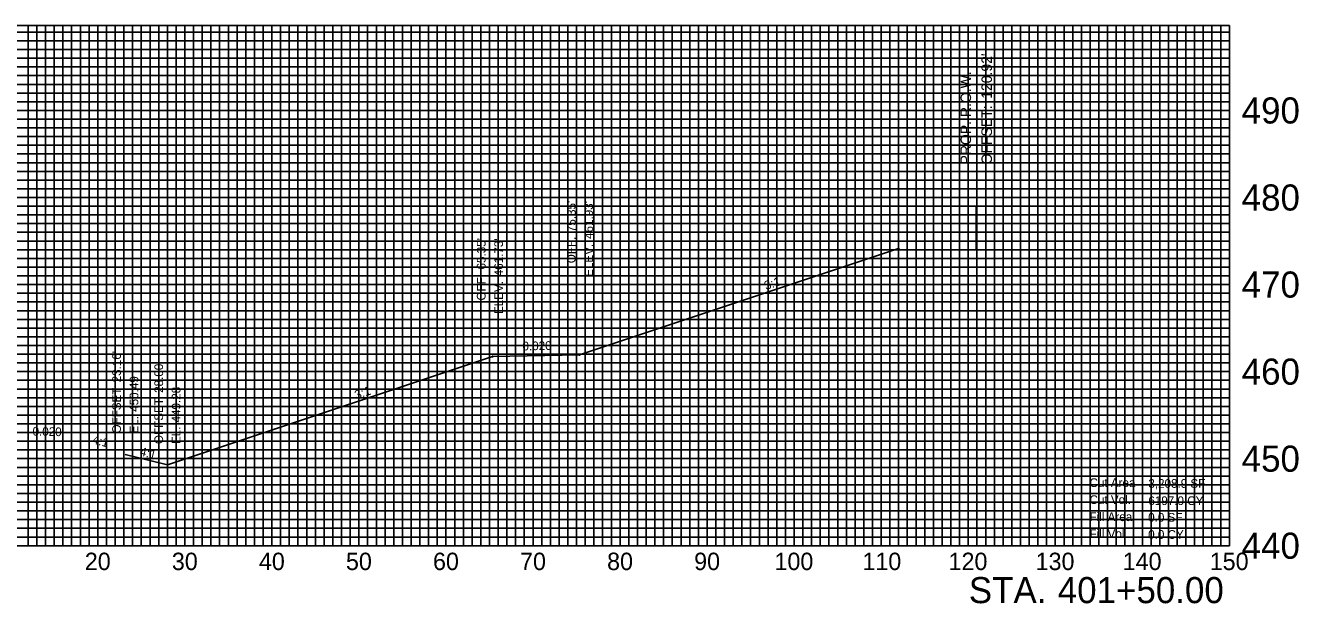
# Model space of a CAD drawing. Extents: x -158 to 158, y 433 to 504.
# Drawn here: x 11.7 to 157.9, y 433.4 to 499.8 of the extents above; entities that cross this region are included whole.
import ezdxf

# ---------------------------------------------------------------- set-up
doc = ezdxf.new("R2010")
doc.units = 0
for name, color, linetype in [('_CIVIL_CONSTRUCTION', 7, 'Continuous'), ('DES - MODEL - CPNT - Grass', 7, 'Continuous'), ('DES - ROW - Linework', 7, 'Continuous'), ('DES - SHEET - Light Grid', 7, 'Continuous'), ('DES - SHEET - Linework', 7, 'Continuous'), ('DES - XS - Earthwork - Cut Text', 7, 'Continuous'), ('DES - XS - Earthwork - Fill Text', 7, 'Continuous'), ('DES - XS - Proposed - Finished Grade Slopes Text', 7, 'Continuous'), ('DES - XS - Proposed - Text', 7, 'Continuous')]:
    doc.layers.add(name, color=color, linetype=linetype)

msp = doc.modelspace()

# ---------------------------------------------------------------- linework, layer by layer
at = {"layer": '_CIVIL_CONSTRUCTION'}
for centre in [(65.35, 461.73), (75.35, 461.93)]:
    msp.add_circle(centre, 0.05, dxfattribs=at)
at = {"layer": 'DES - MODEL - CPNT - Grass'}
for p, q in [((75.35, 461.93), (112.12, 474.18)), ((28, 449.28), (65.35, 461.73)), ((65.35, 461.73), (75.35, 461.93)), ((23.16, 450.49), (28, 449.28))]:
    msp.add_line(p, q, dxfattribs=at)
at = {"layer": 'DES - ROW - Linework'}
msp.add_line((120.92, 473.96), (120.92, 478.88), dxfattribs=at)
at = {"layer": 'DES - SHEET - Light Grid'}
for p, q in [((-150, 499), (150, 499)), ((12, 440), (12, 499.76)), ((13, 440), (13, 499.76)), ((14, 440), (14, 499.76)), ((15, 440), (15, 499.76)), ((16, 440), (16, 499.76)), ((17, 440), (17, 499.76)), ((18, 440), (18, 499.76)), ((19, 440), (19, 499.76)), ((21, 440), (21, 499.76)), ((22, 440), (22, 499.76)), ((23, 440), (23, 499.76)), ((24, 440), (24, 499.76)), ((25, 440), (25, 499.76)), ((26, 440), (26, 499.76)), ((27, 440), (27, 499.76)), ((28, 440), (28, 499.76)), ((29, 440), (29, 499.76)), ((31, 440), (31, 499.76)), ((32, 440), (32, 499.76)), ((33, 440), (33, 499.76)), ((34, 440), (34, 499.76)), ((35, 440), (35, 499.76)), ((36, 440), (36, 499.76)), ((37, 440), (37, 499.76)), ((38, 440), (38, 499.76)), ((39, 440), (39, 499.76)), ((41, 440), (41, 499.76)), ((42, 440), (42, 499.76)), ((43, 440), (43, 499.76)), ((44, 440), (44, 499.76)), ((45, 440), (45, 499.76)), ((46, 440), (46, 499.76)), ((47, 440), (47, 499.76)), ((48, 440), (48, 499.76)), ((49, 440), (49, 499.76)), ((51, 440), (51, 499.76)), ((52, 440), (52, 499.76)), ((53, 440), (53, 499.76)), ((54, 440), (54, 499.76)), ((55, 440), (55, 499.76)), ((56, 440), (56, 499.76)), ((57, 440), (57, 499.76)), ((58, 440), (58, 499.76)), ((59, 440), (59, 499.76)), ((61, 440), (61, 499.76)), ((62, 440), (62, 499.76)), ((63, 440), (63, 499.76)), ((64, 440), (64, 499.76)), ((65, 440), (65, 499.76)), ((66, 440), (66, 499.76)), ((67, 440), (67, 499.76)), ((68, 440), (68, 499.76)), ((69, 440), (69, 499.76)), ((71, 440), (71, 499.76)), ((72, 440), (72, 499.76)), ((73, 440), (73, 499.76)), ((74, 440), (74, 499.76)), ((75, 440), (75, 499.76)), ((76, 440), (76, 499.76)), ((77, 440), (77, 499.76)), ((78, 440), (78, 499.76)), ((79, 440), (79, 499.76)), ((81, 440), (81, 499.76)), ((82, 440), (82, 499.76)), ((83, 440), (83, 499.76)), ((84, 440), (84, 499.76)), ((85, 440), (85, 499.76)), ((86, 440), (86, 499.76)), ((87, 440), (87, 499.76)), ((88, 440), (88, 499.76)), ((89, 440), (89, 499.76)), ((91, 440), (91, 499.76)), ((92, 440), (92, 499.76)), ((93, 440), (93, 499.76)), ((94, 440), (94, 499.76)), ((95, 440), (95, 499.76)), ((96, 440), (96, 499.76)), ((97, 440), (97, 499.76)), ((98, 440), (98, 499.76)), ((99, 440), (99, 499.76)), ((101, 440), (101, 499.76)), ((102, 440), (102, 499.76)), ((103, 440), (103, 499.76)), ((104, 440), (104, 499.76)), ((105, 440), (105, 499.76)), ((106, 440), (106, 499.76)), ((107, 440), (107, 499.76)), ((108, 440), (108, 499.76)), ((109, 440), (109, 499.76)), ((111, 440), (111, 499.76)), ((112, 440), (112, 499.76)), ((113, 440), (113, 499.76)), ((114, 440), (114, 499.76)), ((115, 440), (115, 499.76)), ((116, 440), (116, 499.76)), ((117, 440), (117, 499.76)), ((118, 440), (118, 499.76)), ((119, 440), (119, 499.76)), ((121, 440), (121, 499.76)), ((122, 440), (122, 499.76)), ((123, 440), (123, 499.76)), ((124, 440), (124, 499.76)), ((125, 440), (125, 499.76)), ((126, 440), (126, 499.76)), ((127, 440), (127, 499.76)), ((128, 440), (128, 499.76)), ((129, 440), (129, 499.76)), ((131, 440), (131, 499.76)), ((132, 440), (132, 499.76)), ((133, 440), (133, 499.76)), ((134, 440), (134, 499.76)), ((135, 440), (135, 499.76)), ((136, 440), (136, 499.76)), ((137, 440), (137, 499.76)), ((138, 440), (138, 499.76)), ((139, 440), (139, 499.76)), ((141, 440), (141, 499.76)), ((142, 440), (142, 499.76)), ((143, 440), (143, 499.76)), ((144, 440), (144, 499.76)), ((145, 440), (145, 499.76)), ((146, 440), (146, 499.76)), ((147, 440), (147, 499.76)), ((148, 440), (148, 499.76)), ((149, 440), (149, 499.76)), ((-150, 498), (150, 498)), ((-150, 497), (150, 497)), ((-150, 496), (150, 496)), ((-150, 495), (150, 495)), ((-150, 494), (150, 494)), ((-150, 493), (150, 493)), ((-150, 492), (150, 492)), ((-150, 491), (150, 491)), ((-150, 489), (150, 489)), ((-150, 488), (150, 488)), ((-150, 487), (150, 487)), ((-150, 486), (150, 486)), ((-150, 485), (150, 485)), ((-150, 484), (150, 484)), ((-150, 483), (150, 483)), ((-150, 482), (150, 482)), ((-150, 481), (150, 481)), ((-150, 479), (150, 479)), ((-150, 478), (150, 478)), ((-150, 477), (150, 477)), ((-150, 476), (150, 476)), ((-150, 475), (150, 475)), ((-150, 474), (150, 474)), ((-150, 473), (150, 473)), ((-150, 472), (150, 472)), ((-150, 471), (150, 471)), ((-150, 469), (150, 469)), ((-150, 468), (150, 468)), ((-150, 467), (150, 467)), ((-150, 466), (150, 466)), ((-150, 465), (150, 465)), ((-150, 464), (150, 464)), ((-150, 463), (150, 463)), ((-150, 462), (150, 462)), ((-150, 461), (150, 461)), ((-150, 459), (150, 459)), ((-150, 458), (150, 458)), ((-150, 457), (150, 457)), ((-150, 456), (150, 456)), ((-150, 455), (150, 455)), ((-150, 454), (150, 454)), ((-150, 453), (150, 453)), ((-150, 452), (150, 452)), ((-150, 451), (150, 451)), ((-150, 449), (150, 449)), ((-150, 448), (150, 448)), ((-150, 447), (150, 447)), ((-150, 446), (150, 446)), ((-150, 445), (150, 445)), ((-150, 444), (150, 444)), ((-150, 443), (150, 443)), ((-150, 442), (150, 442)), ((-150, 441), (150, 441))]:
    msp.add_line(p, q, dxfattribs=at)
at = {"layer": 'DES - SHEET - Linework'}
for p, q in [((-150, 499.76), (150, 499.76)), ((20, 440), (20, 499.76)), ((30, 440), (30, 499.76)), ((40, 440), (40, 499.76)), ((50, 440), (50, 499.76)), ((60, 440), (60, 499.76)), ((70, 440), (70, 499.76)), ((80, 440), (80, 499.76)), ((90, 440), (90, 499.76)), ((100, 440), (100, 499.76)), ((110, 440), (110, 499.76)), ((120, 440), (120, 499.76)), ((130, 440), (130, 499.76)), ((140, 440), (140, 499.76)), ((150, 440), (150, 499.76)), ((-150, 490), (150, 490)), ((-150, 480), (150, 480)), ((-150, 470), (150, 470)), ((-150, 460), (150, 460)), ((-150, 450), (150, 450)), ((-150, 440), (150, 440))]:
    msp.add_line(p, q, dxfattribs=at)

# ---------------------------------------------------------------- texts
at = {"layer": 'DES - ROW - Linework'}
for s, p in [("120.92'", (122.72, 491.34)), ('PROP. R.O.W.', (120.32, 483.8)), ('OFFSET: ', (122.72, 483.8))]:
    msp.add_text(s, height=1.2, rotation=90, dxfattribs=at).set_placement(p)
at = {"layer": 'DES - XS - Earthwork - Cut Text'}
for s, p in [('Cut Area', (133.93, 446.74)), ('3,208.9 SF', (140.69, 446.65)), ('Cut Vol.', (133.93, 444.79)), ('6197.0 CY', (140.69, 444.67))]:
    msp.add_text(s, height=1, dxfattribs=at).set_placement(p)
at = {"layer": 'DES - XS - Earthwork - Fill Text'}
for s, p in [('Fill Area', (133.93, 442.83)), ('0.0 SF', (140.67, 442.76)), ('Fill Vol.', (133.93, 440.88)), ('0.0 CY', (140.67, 440.79))]:
    msp.add_text(s, height=1, dxfattribs=at).set_placement(p)
at = {"layer": 'DES - XS - Proposed - Finished Grade Slopes Text'}
for s, rotation, p in [('3:1', 18.4332, (96.76, 469.37)), ('0.020', 1.1458, (68.8, 462.43)), ('3:1', 18.4332, (49.7, 456.81)), ('-0.020', 358.8542, (12.05, 452.66)), ('4:1', 345.9638, (19.3, 451.75)), ('4:1', 345.9638, (24.76, 450.39))]:
    msp.add_text(s, height=1, rotation=rotation, dxfattribs=at).set_placement(p)
at = {"layer": 'DES - XS - Proposed - Text'}
for s, height, p in [('490', 3, (151.41, 488.5)), ('480', 3, (151.41, 478.5)), ('470', 3, (151.41, 468.5)), ('460', 3, (151.41, 458.5)), ('450', 3, (151.41, 448.5)), ('440', 3, (151.41, 438.5)), ('20', 2, (18.51, 437.2)), ('30', 2, (28.51, 437.2)), ('40', 2, (38.51, 437.2)), ('50', 2, (48.51, 437.2)), ('60', 2, (58.51, 437.2)), ('70', 2, (68.51, 437.2)), ('80', 2, (78.51, 437.2)), ('90', 2, (88.51, 437.2)), ('100', 2, (97.74, 437.2)), ('110', 2, (107.84, 437.2)), ('120', 2, (117.74, 437.2)), ('130', 2, (127.74, 437.2)), ('140', 2, (137.74, 437.2)), ('150', 2, (147.74, 437.2)), (' STA. ', 3, (118.95, 433.4)), ('401+50.00', 3, (130.28, 433.4))]:
    msp.add_text(s, height=height, dxfattribs=at).set_placement(p)
for s, p in [("75.35'", (74.9, 476.02)), ("461.93'", (76.9, 475.24)), ('OFF. ', (74.9, 472.45)), ("65.35'", (64.55, 471.73)), ("461.73'", (66.55, 470.95)), ('ELEV. ', (76.9, 470.89)), ('OFF. ', (64.55, 468.16)), ('ELEV. ', (66.55, 466.61)), ("23.16'", (22.66, 458.77)), ("28.00'", (27.5, 457.56)), ('450.49', (24.66, 455.38)), ('OFFSET ', (22.66, 452.89)), ('449.28', (29.5, 454.16)), ('OFFSET ', (27.5, 451.68)), ('EL. ', (24.66, 452.89)), ('EL. ', (29.5, 451.68))]:
    msp.add_text(s, height=1, rotation=90, dxfattribs=at).set_placement(p)

doc.saveas('drawing.dxf')
